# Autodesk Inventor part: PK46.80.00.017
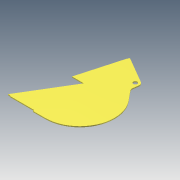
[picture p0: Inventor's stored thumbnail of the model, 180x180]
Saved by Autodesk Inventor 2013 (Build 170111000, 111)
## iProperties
Shininess: 64.0
Length Units: 11269
Angle Units: 11279
Time Units: 11290
Mass Units: 11283
Length Display Precision: 3
Angle Display Precision: 2
Compacted: True
Part Number: PK46.80.00.017
Document SubType Name: Modeling
Created: 2004-12
Material: Steel, Mild
Designer: Salex
Manufacturer: Standard
Standards Organization: Custom
Density: 7.86 g/cm^3
Mass: 57972.3 g
Surface Area: 12737.7 cm^2
Volume: 7375.62 cm^3
Density: 0.0
Volumn: 0.0
Area: 0.0
PropertySet Name: Model Information
Control State: 0
Master: False
Checked Out: False
Checked Out Date: 2008-10-15
Last Check In Date: 2008-10-15
d0: 425.000 mm
d35: 270.000 mm
d36: 420.000 mm
d10: 1155.000 mm
d11: 12.000 mm
d12: 0.00 deg
d13: 150.000 mm
d14: 450.000 mm
d15: 25.000 mm
d16: 17.000 mm
d17: 605.000 mm
d18: 50.000 mm
d19: 50.000 mm
d20: 500.000 mm
d21: 180.000 mm
d22: 205.000 mm
d23: 350.000 mm
d24: 480.000 mm
d25: 350.000 mm
d26: 1125.000 mm
d27: 365.000 mm
Author: Salex
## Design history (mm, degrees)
sketch "Sketch1"
  geometry: L1 (-384.873, 16.042)-(-239.873, 536.042); L2 (-239.873, 536.042)-(-224.873, 566.042); L3 (-224.873, 566.042)-(95.324, 379.229); L4 (-109.873, -588.958)-(-259.873, -588.958); L5 (-589.873, -563.958)-(-239.873, 16.042); L6 (-239.873, 16.042)-(-384.873, 16.042); L7 (-589.873, -563.958)-(-559.873, -563.958); L8 (-559.873, -563.958)-(-559.873, -571.958); L9 (-559.873, -571.958)-(-259.873, -571.958); L10 (-259.873, -571.958)-(-259.873, -588.958); L11 (-239.873, 16.042)-(-149.815, -38.304); L12 (218.934, 105.321)-(121.444, 224.362); L13 (110.587, 262.81)-(119.667, 329.274); C1 r 25 at (70.127, 336.042); A1 r 425 centre (-109.873, -163.958) between (-109.873, -588.958) and (218.934, 105.321); A2 r 50 centre (70.127, 336.042) between (119.667, 329.274) and (95.324, 379.229); A3 r 50 centre (160.127, 256.042) between (110.587, 262.81) and (121.444, 224.362); 1 further point
  constraints: 26 end point, 6 point on circle, 6 tangent, 4 centre point, 3 perpendicular, 2 parallel, 1 concentric, 1 equal radius, 1 horizontal, 1 point on line, 1 other
  dimensions: "d0" = 425 radius of A1; "d10" = 1155 distance from line of L2.end L4; "d13" = 150 distance from line of L10 A1.centre; "d14" = 450 distance from line of L8 A1.centre; "d15" = 25 distance from line of L5.start L4; "d16" = 17 distance between parallel lines of L9 L4; "d17" = 605 distance between parallel lines of L6 L4; "d18" = 50 radius of A2; "d19" = 50 diameter of C1; "d20" = 500 vertical distance of C1.centre A1.centre; "d21" = 180 horizontal distance of C1.centre A1.centre; "d22" = 205 horizontal distance of L1.start L5.start; "d23" = 350 horizontal distance of L5.end L5.start; "d24" = 480 horizontal distance of L5.start A1.centre; "d25" = 350 horizontal distance of L1.end L5.start; "d26" = 1125 distance from line of L1.end L4; "d27" = 365 horizontal distance of L2.end L5.start; "d28" = 124.14721 distance from line of L1.start L5 (derived); "d29" = 677.42158 distance of L5.start L5.end (derived); "d30" = 74.91642 distance from line of L1.start L11 (derived); "d35" = 270 horizontal distance of A3.centre A1.centre; "d36" = 420 vertical distance of A3.centre A1.centre
extrude "Extrusion1" new body sketch "Sketch1" distance "d11" = 12; taper "d12" = 0 deg
body "Solid1"
